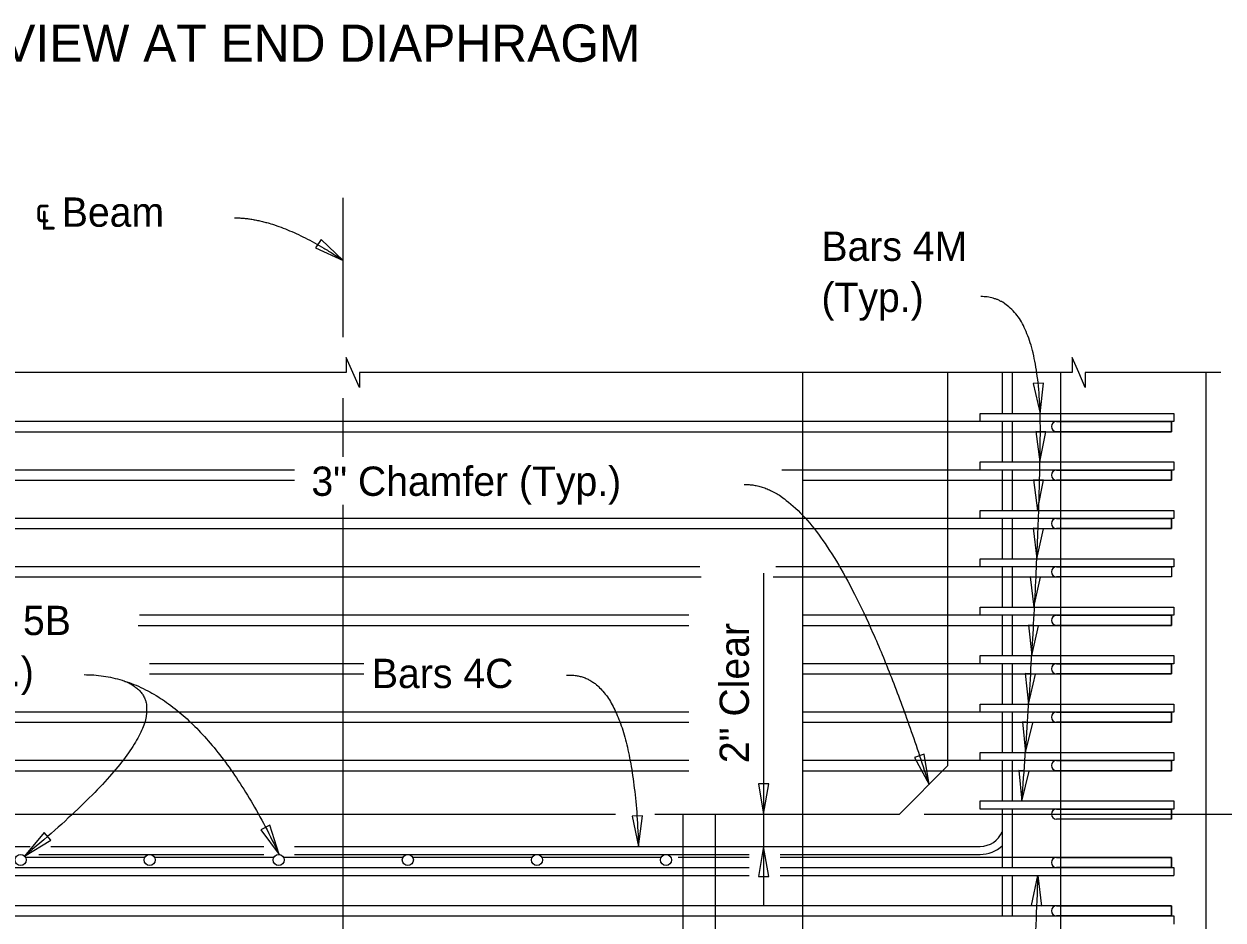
# Model space of a CAD drawing. Extents: x 120658.6 to 120712.1, y 120647.1 to 120669.9.
# Drawn here: x 120663.4 to 120669.6, y 120653.56 to 120658.18 of the extents above; entities that cross this region are included whole.
import ezdxf

# ---------------------------------------------------------------- set-up
doc = ezdxf.new("R2010")
doc.units = 0
for name, color, linetype in [('BeamConc', 7, 'Continuous'), ('BeamConc_h', 7, 'Continuous'), ('CL_Major', 7, 'Continuous'), ('Dimension', 7, 'Continuous'), ('Miscellaneous', 7, 'Continuous'), ('Rebar', 7, 'Continuous'), ('Rebar_h', 7, 'Continuous'), ('TextStructures', 7, 'Continuous')]:
    doc.layers.add(name, color=color, linetype=linetype)

msp = doc.modelspace()

# ---------------------------------------------------------------- linework, layer by layer
at = {"layer": 'BeamConc'}
for p, q in [((120668.175, 120654.3531), (120668.175, 120656.3833)), ((120669.5083, 120652.1656), (120669.5083, 120656.3833)), ((120667.925, 120654.1031), (120668.175, 120654.3531)), ((120662.2583, 120654.1031), (120666.4578, 120654.1031)), ((120666.6615, 120654.1031), (120667.925, 120654.1031))]:
    msp.add_line(p, q, dxfattribs=at)
at = {"layer": 'BeamConc_h'}
for p, q in [((120667.425, 120656.3833), (120667.425, 120652.1031)), ((120668.7583, 120652.1656), (120668.7583, 120656.3833))]:
    msp.add_line(p, q, dxfattribs=at)
at = {"layer": 'CL_Major'}
for p, q in [((120665.0529, 120656.5645), (120665.0529, 120657.2837)), ((120665.0529, 120655.9468), (120665.0529, 120656.2507)), ((120665.0529, 120650.8078), (120665.0529, 120655.6993))]:
    msp.add_line(p, q, dxfattribs=at)
at = {"layer": 'Dimension'}
for p, q in [((120667.2231, 120655.3466), (120667.2231, 120653.6341)), ((120667.2987, 120654.1031), (120667.2987, 120654.1031)), ((120668.0525, 120654.1031), (120670.5839, 120654.1031)), ((120667.2987, 120653.9365), (120667.2987, 120653.9365))]:
    msp.add_line(p, q, dxfattribs=at)
for points in [[(120665.0529, 120656.9608), (120664.938, 120657.0698), (120664.9085, 120657.0259)], [(120668.6511, 120656.1709), (120668.6689, 120656.3283), (120668.6161, 120656.3254)], [(120668.6507, 120655.9209), (120668.6817, 120656.0762), (120668.6288, 120656.0778)], [(120668.6383, 120655.6709), (120668.6694, 120655.8262), (120668.6165, 120655.8278)], [(120668.6346, 120655.4209), (120668.6687, 120655.5756), (120668.6159, 120655.5782)], [(120668.6185, 120655.1709), (120668.6526, 120655.3256), (120668.5998, 120655.3282)], [(120668.6084, 120654.9209), (120668.6439, 120655.0753), (120668.5911, 120655.0783)], [(120668.5915, 120654.6709), (120668.6269, 120654.8253), (120668.5741, 120654.8283)], [(120668.5752, 120654.4209), (120668.6134, 120654.5746), (120668.5606, 120654.5786)], [(120668.0776, 120654.2557), (120668.053, 120654.4122), (120668.0028, 120654.3954)], [(120668.5568, 120654.1704), (120668.595, 120654.3241), (120668.5422, 120654.3281)], [(120667.2231, 120654.1031), (120667.2497, 120654.2587), (120667.1964, 120654.2587)], [(120666.5779, 120653.9365), (120666.5981, 120654.0936), (120666.5452, 120654.0915)], [(120663.4067, 120653.8861), (120663.542, 120653.9685), (120663.5074, 120654.0084)], [(120664.722, 120653.8947), (120664.6737, 120654.0456), (120664.6267, 120654.0212)], [(120667.2231, 120653.9364), (120667.1964, 120653.7807), (120667.2497, 120653.7807)], [(120668.6397, 120653.7854), (120668.6594, 120653.6282), (120668.6065, 120653.6305)]]:
    msp.add_lwpolyline(points, close=True, dxfattribs=at)
for points in [[(120668.0994, 120656.3833), (120665.1358, 120656.3833), (120665.1358, 120656.3058), (120665.102, 120656.3833), (120665.0683, 120656.4608), (120665.0683, 120656.3833), (120662.0839, 120656.3833)], [(120669.5839, 120656.3833), (120668.8846, 120656.3833), (120668.8846, 120656.3058), (120668.8509, 120656.3833), (120668.8171, 120656.4608), (120668.8171, 120656.3833), (120668.0994, 120656.3833)]]:
    msp.add_lwpolyline(points, dxfattribs=at)
for points in [[(120664.4904, 120657.181), (120664.7248, 120657.181), (120665.0529, 120656.9608)], [(120668.5572, 120654.1709), (120668.647, 120655.3573), (120668.6582, 120656.7709), (120668.346, 120656.7747)], [(120667.1238, 120655.804), (120667.5781, 120655.8191), (120668.0776, 120654.2557)], [(120663.7148, 120654.8229), (120664.2806, 120654.8229), (120664.722, 120653.8947)], [(120666.2048, 120654.8195), (120666.545, 120654.846), (120666.5779, 120653.9365)], [(120663.9139, 120654.7933), (120664.3187, 120654.6431), (120663.4067, 120653.8861)], [(120668.6397, 120653.7854), (120668.5921, 120652.6793), (120668.6046, 120651.6182), (120668.7732, 120651.6494)]]:
    msp.add_open_spline(points, degree=2, dxfattribs=at)
at = {"layer": 'Miscellaneous'}
for p, q in [((120666.8065, 120654.1031), (120666.8065, 120652.1031)), ((120666.9732, 120654.1031), (120666.9732, 120652.1031))]:
    msp.add_line(p, q, dxfattribs=at)
at = {"layer": 'Rebar'}
for p, q in [((120668.4563, 120656.1709), (120668.4563, 120656.3833)), ((120668.5083, 120656.1709), (120668.5083, 120656.3833)), ((120668.3416, 120656.1709), (120669.3417, 120656.1709)), ((120668.3416, 120656.1292), (120668.3416, 120656.1709)), ((120669.3417, 120656.1709), (120669.3417, 120656.1292)), ((120669.3417, 120656.1292), (120668.3416, 120656.1292)), ((120668.4563, 120655.9209), (120668.4563, 120656.1292)), ((120668.5083, 120655.9209), (120668.5083, 120656.1292)), ((120668.7363, 120656.1292), (120669.3303, 120656.1292)), ((120669.3303, 120656.1292), (120669.3303, 120656.0771)), ((120669.3303, 120656.0771), (120668.7363, 120656.0771)), ((120668.3416, 120655.9209), (120669.3417, 120655.9209)), ((120668.3416, 120655.8792), (120668.3416, 120655.9209)), ((120669.3417, 120655.9209), (120669.3417, 120655.8792)), ((120669.3417, 120655.8792), (120668.3416, 120655.8792)), ((120668.4563, 120655.6709), (120668.4563, 120655.8792)), ((120668.5083, 120655.6709), (120668.5083, 120655.8792)), ((120668.7363, 120655.8792), (120669.3303, 120655.8792)), ((120669.3303, 120655.8792), (120669.3303, 120655.8271)), ((120669.3303, 120655.8271), (120668.7363, 120655.8271)), ((120668.3416, 120655.6709), (120669.3417, 120655.6709)), ((120668.3416, 120655.6292), (120668.3416, 120655.6709)), ((120669.3417, 120655.6709), (120669.3417, 120655.6292)), ((120669.3417, 120655.6292), (120668.3416, 120655.6292)), ((120668.4563, 120655.4209), (120668.4563, 120655.6292)), ((120668.5083, 120655.4209), (120668.5083, 120655.6292)), ((120668.7363, 120655.6292), (120669.3303, 120655.6292)), ((120669.3303, 120655.6292), (120669.3303, 120655.5771)), ((120669.3303, 120655.5771), (120668.7363, 120655.5771)), ((120668.3416, 120655.4209), (120669.3417, 120655.4209)), ((120668.3416, 120655.3792), (120668.3416, 120655.4209)), ((120669.3417, 120655.4209), (120669.3417, 120655.3792)), ((120669.3417, 120655.3792), (120668.3416, 120655.3792)), ((120668.4563, 120655.1709), (120668.4563, 120655.3792)), ((120668.5083, 120655.1709), (120668.5083, 120655.3792)), ((120668.7363, 120655.3792), (120669.3303, 120655.3792)), ((120669.3303, 120655.3792), (120669.3303, 120655.3271)), ((120669.3303, 120655.3271), (120668.7363, 120655.3271)), ((120668.3416, 120655.1709), (120669.3417, 120655.1709)), ((120668.3416, 120655.1292), (120668.3416, 120655.1709)), ((120669.3417, 120655.1292), (120668.3416, 120655.1292)), ((120668.4563, 120654.9209), (120668.4563, 120655.1292)), ((120668.5083, 120654.9209), (120668.5083, 120655.1292)), ((120668.7363, 120655.1292), (120669.3303, 120655.1292)), ((120669.3303, 120655.1292), (120669.3303, 120655.0771)), ((120669.3417, 120655.1709), (120669.3417, 120655.1292)), ((120669.3303, 120655.0771), (120668.7363, 120655.0771)), ((120668.3416, 120654.9209), (120669.3417, 120654.9209)), ((120668.3416, 120654.8792), (120668.3416, 120654.9209)), ((120669.3417, 120654.8792), (120668.3416, 120654.8792)), ((120668.4563, 120654.6709), (120668.4563, 120654.8792)), ((120668.5083, 120654.6709), (120668.5083, 120654.8792)), ((120668.7363, 120654.8792), (120669.3303, 120654.8792)), ((120669.3303, 120654.8792), (120669.3303, 120654.8271)), ((120669.3417, 120654.9209), (120669.3417, 120654.8792)), ((120669.3303, 120654.8271), (120668.7363, 120654.8271)), ((120668.3416, 120654.6709), (120669.3417, 120654.6709)), ((120668.3416, 120654.6292), (120668.3416, 120654.6709)), ((120669.3417, 120654.6292), (120668.3416, 120654.6292)), ((120668.4563, 120654.4209), (120668.4563, 120654.6292)), ((120668.5083, 120654.4209), (120668.5083, 120654.6292)), ((120668.7363, 120654.6292), (120669.3303, 120654.6292)), ((120669.3303, 120654.6292), (120669.3303, 120654.5771)), ((120669.3417, 120654.6709), (120669.3417, 120654.6292)), ((120669.3303, 120654.5771), (120668.7363, 120654.5771)), ((120668.3416, 120654.4209), (120669.3417, 120654.4209)), ((120668.3416, 120654.3792), (120668.3416, 120654.4209)), ((120669.3417, 120654.3792), (120668.3416, 120654.3792)), ((120668.4563, 120654.1709), (120668.4563, 120654.3792)), ((120668.5083, 120654.1709), (120668.5083, 120654.3792)), ((120668.7363, 120654.3792), (120669.3303, 120654.3792)), ((120669.3303, 120654.3792), (120669.3303, 120654.3271)), ((120669.3417, 120654.4209), (120669.3417, 120654.3792)), ((120669.3303, 120654.3271), (120668.7363, 120654.3271)), ((120668.3416, 120654.1709), (120669.3417, 120654.1709)), ((120668.3416, 120654.1292), (120668.3416, 120654.1709)), ((120669.3417, 120654.1292), (120668.3416, 120654.1292)), ((120668.4563, 120653.8271), (120668.4563, 120654.1292)), ((120668.5083, 120653.8271), (120668.5083, 120654.1292)), ((120668.7363, 120654.1292), (120669.3303, 120654.1292)), ((120669.3303, 120654.1292), (120669.3303, 120654.0771)), ((120669.3417, 120654.1709), (120669.3417, 120654.1292)), ((120669.3303, 120654.0771), (120668.7363, 120654.0771)), ((120661.8417, 120653.9365), (120663.4354, 120653.9365)), ((120663.5426, 120653.9365), (120664.6432, 120653.9365)), ((120664.801, 120653.9365), (120668.3416, 120653.9365)), ((120663.4803, 120653.8948), (120664.6432, 120653.8948)), ((120664.801, 120653.8948), (120667.1494, 120653.8948)), ((120667.3094, 120653.8948), (120668.3415, 120653.8948)), ((120668.7363, 120653.8792), (120669.3303, 120653.8792)), ((120669.3303, 120653.8792), (120669.3303, 120653.8271)), ((120660.8417, 120653.8271), (120667.1494, 120653.8271)), ((120667.3094, 120653.8271), (120669.3417, 120653.8271)), ((120669.3303, 120653.8271), (120668.7363, 120653.8271)), ((120669.3417, 120653.8271), (120669.3417, 120653.7854)), ((120660.8417, 120653.7854), (120667.1494, 120653.7854)), ((120667.3094, 120653.7854), (120669.3417, 120653.7854)), ((120668.4563, 120653.5771), (120668.4563, 120653.7854)), ((120668.5083, 120653.5771), (120668.5083, 120653.7854)), ((120668.7363, 120653.6292), (120669.3303, 120653.6292)), ((120669.3303, 120653.6292), (120669.3303, 120653.5771)), ((120660.8417, 120653.5771), (120669.3417, 120653.5771)), ((120669.3303, 120653.5771), (120668.7363, 120653.5771)), ((120669.3417, 120653.5771), (120669.3417, 120653.5354))]:
    msp.add_line(p, q, dxfattribs=at)
for centre in [(120663.3862, 120653.8661), (120664.0529, 120653.8661), (120664.7195, 120653.8661), (120665.3862, 120653.8661), (120666.0529, 120653.8661), (120666.7195, 120653.8661)]:
    msp.add_circle(centre, 0.0287, dxfattribs=at)
for centre, radius, start, end in [((120668.7363, 120656.1032), 0.026, 90, 270), ((120668.7363, 120655.8532), 0.026, 90, 270), ((120668.7363, 120655.6032), 0.026, 90, 270), ((120668.7363, 120655.3532), 0.026, 90, 270), ((120668.7363, 120655.1032), 0.026, 90, 270), ((120668.7363, 120654.8532), 0.026, 90, 270), ((120668.7363, 120654.6032), 0.026, 90, 270), ((120668.7363, 120654.3532), 0.026, 90, 270), ((120668.7363, 120654.1032), 0.026, 90, 270), ((120668.3416, 120654.0615), 0.125, 270, 336.48194), ((120668.3417, 120654.0615), 0.1667, 270, 313.43255), ((120668.7363, 120653.8532), 0.026, 90, 270), ((120668.7363, 120653.6032), 0.026, 90, 270)]:
    msp.add_arc(centre, radius, start, end, dxfattribs=at)
at = {"layer": 'Rebar_h'}
msp.add_line((120669.3303, 120654.0771), (120669.3303, 120654.1292), dxfattribs=at)
for points in [[(120669.3303, 120656.1292), (120660.8531, 120656.1292), (120660.8531, 120656.0771), (120669.3303, 120656.0771)], [(120669.3303, 120655.6292), (120660.8531, 120655.6292), (120660.8531, 120655.5771), (120669.3303, 120655.5771)]]:
    msp.add_lwpolyline(points, close=True, dxfattribs=at)
for points in [[(120664.8016, 120655.8792), (120660.8531, 120655.8792), (120660.8531, 120655.8271), (120664.8016, 120655.8271)], [(120667.424, 120655.8271), (120669.3303, 120655.8271), (120669.3303, 120655.8792), (120667.3179, 120655.8792)], [(120666.894, 120655.3792), (120660.8531, 120655.3792), (120660.8531, 120655.3271), (120666.9015, 120655.3271)], [(120668.3416, 120655.3792), (120667.2866, 120655.3792)], [(120667.2734, 120655.3271), (120668.7583, 120655.3271)], [(120666.8374, 120655.1292), (120663.9998, 120655.1292)], [(120667.424, 120655.0771), (120669.3303, 120655.0771), (120669.3303, 120655.1292), (120667.424, 120655.1292)], [(120663.9932, 120655.0771), (120666.8374, 120655.0771)], [(120665.1581, 120654.8792), (120664.0529, 120654.8792)], [(120667.424, 120654.8271), (120669.3303, 120654.8271), (120669.3303, 120654.8792), (120667.424, 120654.8792)], [(120664.0529, 120654.8271), (120665.1581, 120654.8271)], [(120666.8374, 120654.6292), (120660.8531, 120654.6292), (120660.8531, 120654.5771), (120666.8374, 120654.5771)], [(120667.424, 120654.5771), (120669.3303, 120654.5771), (120669.3303, 120654.6292), (120667.424, 120654.6292)], [(120666.8374, 120654.3792), (120660.8531, 120654.3792), (120660.8531, 120654.3271), (120666.8374, 120654.3271)], [(120667.424, 120654.3271), (120669.3303, 120654.3271), (120669.3303, 120654.3792), (120667.424, 120654.3792)], [(120664.029, 120653.8792), (120663.4101, 120653.8792)], [(120664.6957, 120653.8792), (120664.0767, 120653.8792)], [(120665.3623, 120653.8792), (120664.7434, 120653.8792)], [(120666.029, 120653.8792), (120665.4101, 120653.8792)], [(120666.6957, 120653.8792), (120666.0768, 120653.8792)], [(120667.1494, 120653.8792), (120666.7822, 120653.8792)], [(120667.3094, 120653.8271), (120669.3303, 120653.8271), (120669.3303, 120653.8792), (120667.3094, 120653.8792)], [(120663.4122, 120653.8271), (120664.0268, 120653.8271)], [(120664.0789, 120653.8271), (120664.6935, 120653.8271)], [(120664.7456, 120653.8271), (120665.3602, 120653.8271)], [(120665.4123, 120653.8271), (120666.0268, 120653.8271)], [(120666.0789, 120653.8271), (120666.6935, 120653.8271)], [(120666.7844, 120653.8271), (120667.1494, 120653.8271)], [(120668.3586, 120653.6292), (120660.8531, 120653.6292), (120660.8531, 120653.5771), (120663.399, 120653.5771)], [(120666.7844, 120653.5771), (120669.3303, 120653.5771), (120669.3303, 120653.6292), (120668.3586, 120653.6292)]]:
    msp.add_lwpolyline(points, dxfattribs=at)

# ---------------------------------------------------------------- texts
at = {"layer": 'Dimension'}
for s, p in [('Bars 4M', (120667.5223, 120656.9589)), ('(Typ.)', (120667.5223, 120656.6949))]:
    msp.add_text(s, height=0.1512, dxfattribs=at).set_placement(p)
at = {"layer": 'TextStructures'}
for s, height, p in [('END VIEW AT END DIAPHRAGM', 0.192, (120662.6787, 120657.9867)), ('℄ Beam', 0.1512, (120663.4612, 120657.1349)), ('3" Chamfer (Typ.)', 0.1512, (120664.8882, 120655.7458)), ('Bars 5B', 0.1512, (120662.9271, 120655.0271)), ('(Typ.)', 0.1512, (120662.9271, 120654.7631)), ('Bars 4C', 0.1512, (120665.2008, 120654.7536))]:
    msp.add_text(s, height=height, dxfattribs=at).set_placement(p)
msp.add_text('2" Clear', height=0.1512, rotation=90, dxfattribs=at).set_placement((120667.1475, 120654.366))

doc.saveas('drawing.dxf')
